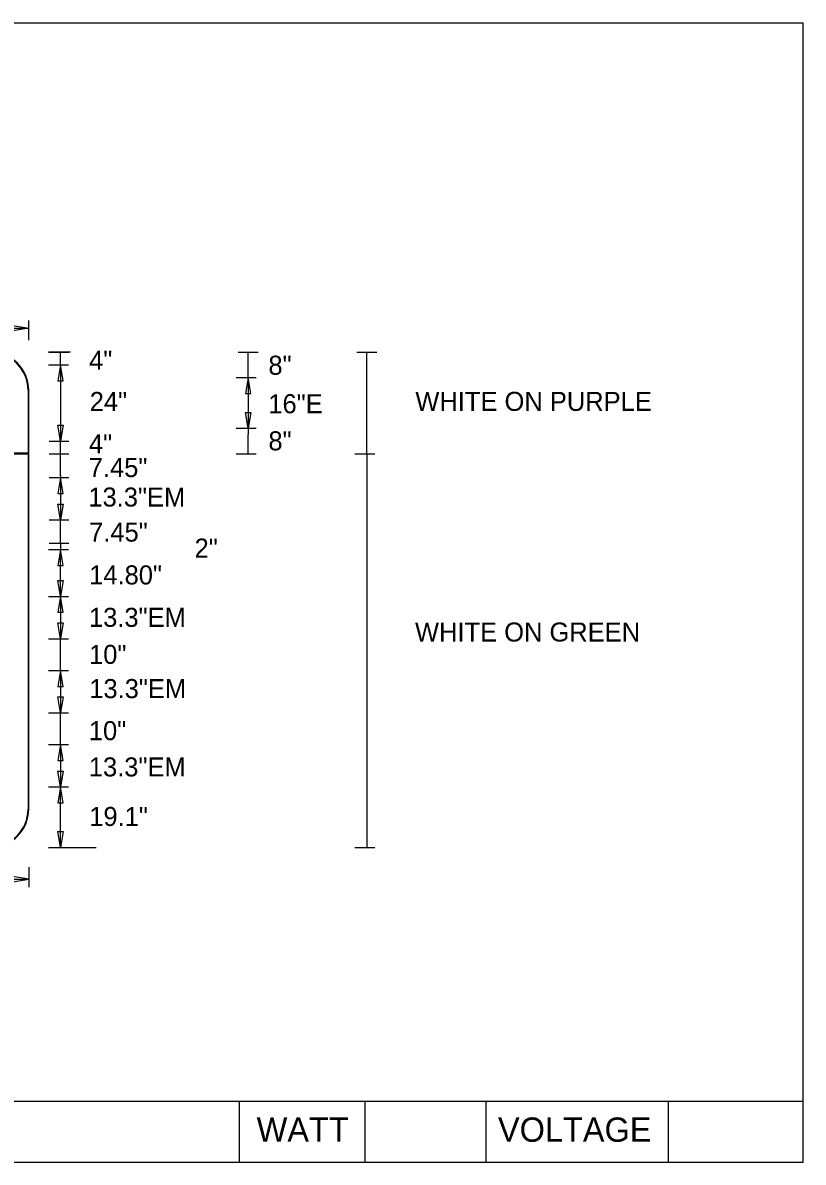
# Model space of a CAD drawing. Extents: x 119523 to 121850, y -23542 to -19972.
# Drawn here: x 120434.4 to 120680.1, y -23086 to -22727.1 of the extents above; entities that cross this region are included whole.
import ezdxf

# ---------------------------------------------------------------- set-up
doc = ezdxf.new("R2010")
doc.units = 0
for name, color, linetype in [('GSBWFill', 7, 'Continuous'), ('GSColorFill', 7, 'Continuous'), ('GSDims', 7, 'Continuous'), ('GSOutline', 7, 'Continuous'), ('SheetLinesMisc2_dp', 7, 'Continuous'), ('TextMinor', 7, 'Continuous')]:
    doc.layers.add(name, color=color, linetype=linetype)

msp = doc.modelspace()

# ---------------------------------------------------------------- linework, layer by layer
at = {"layer": 'GSBWFill'}
for p, q in [((120436.25, -22974.87), (120436.25, -22842.87)), ((120436.25, -22862.87), (120436.25, -22842.87)), ((120178.25, -22862.87), (120436.25, -22862.87))]:
    msp.add_line(p, q, dxfattribs=at)
for centre, start, end in [((120424.25, -22842.87), 0, 90), ((120424.25, -22842.87), 0, 90), ((120424.25, -22974.87), 270, 0)]:
    msp.add_arc(centre, 12, start, end, dxfattribs=at)
at = {"layer": 'GSColorFill'}
for p, q in [((120436.05, -22842.87), (120436.05, -22974.87)), ((120436.05, -22842.87), (120436.05, -22862.67)), ((120436.25, -22974.87), (120436.25, -22842.87)), ((120436.25, -22974.87), (120436.25, -22842.87)), ((120436.25, -22974.87), (120436.25, -22842.87)), ((120436.25, -22862.87), (120436.25, -22842.87)), ((120436.25, -22862.87), (120436.25, -22842.87)), ((120436.25, -22862.87), (120436.25, -22842.87)), ((120436.05, -22862.67), (120178.25, -22862.67)), ((120178.25, -22862.87), (120436.25, -22862.87)), ((120178.25, -22862.87), (120436.25, -22862.87)), ((120178.25, -22862.87), (120436.25, -22862.87))]:
    msp.add_line(p, q, dxfattribs=at)
for centre, radius, start, end in [((120424.25, -22842.87), 12, 0, 90), ((120424.25, -22842.87), 12, 0, 90), ((120424.25, -22842.87), 12, 0, 90), ((120424.25, -22842.87), 12, 0, 90), ((120424.25, -22842.87), 12, 0, 90), ((120424.25, -22842.87), 12, 0, 90), ((120424.25, -22842.87), 11.8, 0, 90), ((120424.25, -22842.87), 11.8, 0, 90), ((120424.25, -22974.87), 12, 270, 0), ((120424.25, -22974.87), 12, 270, 0), ((120424.25, -22974.87), 12, 270, 0), ((120424.25, -22974.87), 11.8, 270, 0)]:
    msp.add_arc(centre, radius, start, end, dxfattribs=at)
at = {"layer": 'GSDims'}
for p, q in [((120436.25, -22827.12), (120436.25, -22820.87)), ((120178.25, -22823.37), (120436.25, -22823.37)), ((120436.25, -22827.12), (120436.25, -22827.12)), ((120442.5, -22830.87), (120448.75, -22830.87)), ((120449.42, -22830.87), (120442.5, -22830.87)), ((120446.25, -22835.07), (120446.25, -22830.87)), ((120502.24, -22830.87), (120508.49, -22830.87)), ((120505.36, -22840.87), (120505.36, -22830.87)), ((120539.62, -22830.87), (120545.87, -22830.87)), ((120542.74, -22862.87), (120542.74, -22830.87)), ((120442.5, -22834.87), (120448.75, -22834.87)), ((120446.25, -22835.07), (120446.25, -22859.07)), ((120501.61, -22838.87), (120507.86, -22838.87)), ((120505.36, -22840.87), (120505.36, -22856.87)), ((120501.61, -22854.87), (120507.86, -22854.87)), ((120505.36, -22862.87), (120505.36, -22856.87)), ((120442.65, -22858.87), (120448.9, -22858.87)), ((120446.25, -22869.85), (120446.25, -22859.07)), ((120442.65, -22862.87), (120448.9, -22862.87)), ((120501.61, -22862.87), (120507.86, -22862.87)), ((120538.99, -22862.87), (120545.24, -22862.87)), ((120542.74, -22862.87), (120542.74, -22986.87)), ((120442.65, -22870.32), (120448.9, -22870.32)), ((120446.25, -22869.85), (120446.25, -22883.18)), ((120446.25, -22891.08), (120446.25, -22883.18)), ((120442.65, -22883.65), (120448.9, -22883.65)), ((120442.5, -22893.08), (120448.75, -22893.08)), ((120442.5, -22893.08), (120448.75, -22893.08)), ((120442.65, -22891.1), (120448.9, -22891.1)), ((120446.25, -22891.08), (120446.25, -22893.08)), ((120446.25, -22907.83), (120446.25, -22893.08)), ((120442.5, -22907.83), (120448.75, -22907.83)), ((120442.5, -22907.83), (120448.75, -22907.83)), ((120446.25, -22907.83), (120446.25, -22921.16)), ((120442.5, -22921.16), (120448.75, -22921.16)), ((120442.5, -22921.16), (120448.75, -22921.16)), ((120446.25, -22931.16), (120446.25, -22921.16)), ((120442.5, -22931.16), (120448.75, -22931.16)), ((120442.5, -22931.16), (120448.75, -22931.16)), ((120446.25, -22931.16), (120446.25, -22944.49)), ((120442.5, -22944.49), (120448.75, -22944.49)), ((120442.5, -22944.49), (120448.75, -22944.49)), ((120446.25, -22954.49), (120446.25, -22944.49)), ((120442.5, -22954.49), (120448.75, -22954.49)), ((120442.5, -22954.49), (120448.75, -22954.49)), ((120446.25, -22954.49), (120446.25, -22967.82)), ((120442.5, -22967.82), (120448.75, -22967.82)), ((120442.5, -22967.82), (120448.75, -22967.82)), ((120446.25, -22986.87), (120446.25, -22967.82)), ((120442.5, -22986.87), (120448.75, -22986.87)), ((120442.5, -22986.87), (120457.5, -22986.87)), ((120538.99, -22986.87), (120545.24, -22986.87)), ((120436.25, -22993.12), (120436.25, -22999.37)), ((120436.25, -22993.12), (120436.25, -22999.37)), ((120418.24, -22996.87), (120436.25, -22996.87))]:
    msp.add_line(p, q, dxfattribs=at)
for points in [[(120436.25, -22823.37), (120431.25, -22824.2), (120431.25, -22822.54)], [(120446.25, -22834.87), (120445.42, -22839.87), (120447.08, -22839.87)], [(120505.36, -22838.87), (120504.53, -22843.87), (120506.19, -22843.87)], [(120505.36, -22854.87), (120504.53, -22849.87), (120506.19, -22849.87)], [(120446.25, -22858.86), (120445.41, -22853.86), (120447.08, -22853.86)], [(120446.25, -22870.4), (120445.42, -22875.4), (120447.08, -22875.4)], [(120446.25, -22883.72), (120445.42, -22878.72), (120447.08, -22878.72)], [(120446.25, -22893.08), (120445.42, -22898.08), (120447.08, -22898.08)], [(120446.25, -22907.83), (120445.42, -22902.83), (120447.08, -22902.83)], [(120446.25, -22907.83), (120445.42, -22912.83), (120447.08, -22912.83)], [(120446.25, -22921.16), (120445.42, -22916.16), (120447.08, -22916.16)], [(120446.25, -22931.16), (120445.42, -22936.16), (120447.08, -22936.16)], [(120446.25, -22944.49), (120445.42, -22939.49), (120447.08, -22939.49)], [(120446.25, -22954.49), (120445.42, -22959.49), (120447.08, -22959.49)], [(120446.25, -22967.82), (120445.42, -22962.82), (120447.08, -22962.82)], [(120446.25, -22967.82), (120445.42, -22972.82), (120447.08, -22972.82)], [(120446.25, -22986.87), (120445.42, -22981.87), (120447.08, -22981.87)], [(120436.25, -22996.87), (120431.25, -22996.04), (120431.25, -22997.7)]]:
    msp.add_lwpolyline(points, close=True, dxfattribs=at)
at = {"layer": 'GSOutline'}
for p, q in [((120436.25, -22974.87), (120436.25, -22842.87)), ((120436.25, -22862.87), (120436.25, -22842.87)), ((120178.25, -22862.87), (120436.25, -22862.87))]:
    msp.add_line(p, q, dxfattribs=at)
for centre, start, end in [((120424.25, -22842.87), 0, 90), ((120424.25, -22842.87), 0, 90), ((120424.25, -22974.87), 270, 0)]:
    msp.add_arc(centre, 12, start, end, dxfattribs=at)
at = {"layer": 'SheetLinesMisc2_dp'}
for p, q in [((119943.36, -22727.16), (120680.14, -22727.16)), ((120680.13, -23085.53), (120680.13, -22727.14)), ((119943.36, -23066.81), (120680.14, -23066.81)), ((120502.57, -23066.81), (120502.57, -23086.04)), ((120542.09, -23066.81), (120542.09, -23086.04)), ((120580.21, -23066.81), (120580.21, -23086.04)), ((120637.59, -23066.81), (120637.59, -23086.04)), ((119943.36, -23086.04), (120680.14, -23086.04)), ((120680.13, -23086.02), (120680.13, -23085.53))]:
    msp.add_line(p, q, dxfattribs=at)

# ---------------------------------------------------------------- texts
at = {"layer": 'GSDims'}
for s, p in [('4"', (120455.28, -22836.45)), ('4"', (120455.22, -22862.73)), ('7.45"', (120455.17, -22870.22)), ('13.3"EM', (120455.05, -22879.52)), ('7.45"', (120455.28, -22890.56)), ('2"', (120488.49, -22895.59)), ('14.80"', (120455.3, -22904.05)), ('13.3"EM', (120455.24, -22917.41)), ('10"', (120455.26, -22929.08)), ('13.3"EM', (120455.33, -22939.86)), ('10"', (120455.2, -22953.11)), ('13.3"EM', (120455.19, -22964.53)), ('19.1"', (120455.33, -22980.13))]:
    msp.add_text(s, height=6, dxfattribs=at).set_placement(p)
for s, p in [('8"', (120511.74, -22838)), ('24"', (120455.47, -22849.42)), ('WHITE ON PURPLE', (120558.01, -22849.39)), ('16"E', (120511.71, -22850.13)), ('8"', (120511.74, -22861.82)), ('WHITE ON GREEN', (120557.9, -22922.04))]:
    msp.add_text(s, height=6, rotation=360, dxfattribs=at).set_placement(p)
at = {"layer": 'TextMinor'}
for s, p in [('WATT', (120508.04, -23079.6)), ('VOLTAGE', (120584.02, -23079.6))]:
    msp.add_text(s, height=7.653, dxfattribs=at).set_placement(p)

doc.saveas('drawing.dxf')
